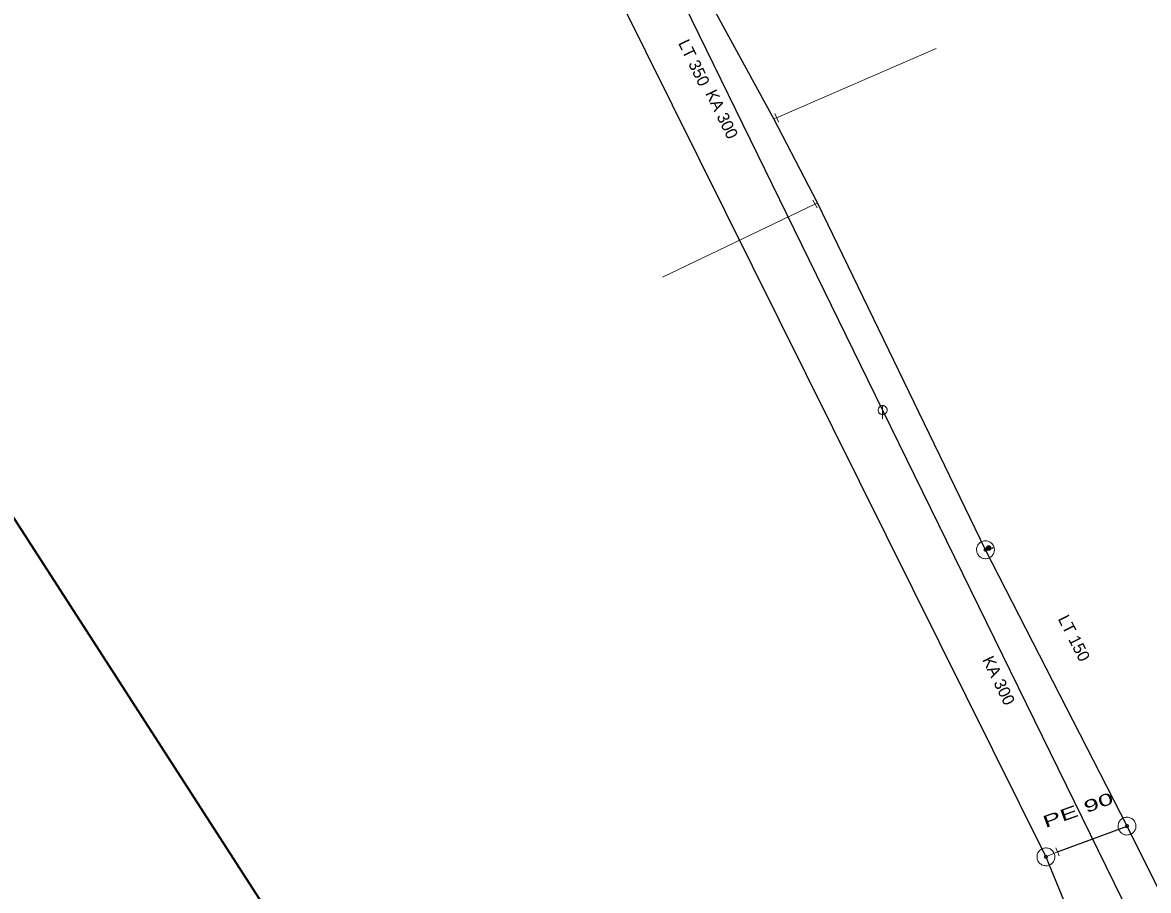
# Model space of a CAD drawing. Extents: x -687468 to -685917, y -974192 to -973456.
# Drawn here: x -686146.9 to -686083.7, y -973629.5 to -973580.8 of the extents above; entities that cross this region are included whole.
import ezdxf
from ezdxf.enums import TextEntityAlignment as Align

# ---------------------------------------------------------------- set-up
doc = ezdxf.new("R2010")
doc.units = 0
doc.header["$LTSCALE"] = 0.27
for name, color, linetype, lineweight in [('1', 7, 'Continuous', 13), ('13', 7, 'Continuous', 13), ('14', 7, 'Continuous', 25), ('17', 7, 'Continuous', 25), ('22', 7, 'Continuous', 13), ('34', 7, 'Continuous', 13), ('47', 7, 'Continuous', 13), ('9', 7, 'Continuous', 13)]:
    doc.layers.add(name, color=color, linetype=linetype, lineweight=lineweight)

msp = doc.modelspace()

# ---------------------------------------------------------------- linework, layer by layer
at = {"layer": '13'}
for p, q in [((-686104.569, -973586.101), (-686095.624, -973582.228)), ((-686102.416, -973590.949), (-686110.964, -973595.047))]:
    msp.add_line(p, q, dxfattribs=at)
at = {"layer": '14', "lineweight": 13}
for p, q in [((-686104.723, -973586.169), (-686104.569, -973586.101)), ((-686102.274, -973590.875), (-686102.416, -973590.949)), ((-686092.851, -973610.351), (-686092.667, -973610.253)), ((-686089.459, -973627.585), (-686088.809, -973627.309))]:
    msp.add_line(p, q, dxfattribs=at)
at = {"layer": '14'}
msp.add_line((-686098.62, -973602.51), (-686082.39, -973635.68), dxfattribs=at)
msp.add_lwpolyline([(-686121.14, -973557.36), (-686113.805, -973571.474), (-686113.469, -973572.12), (-686098.62, -973602.51)], dxfattribs=at)
at = {"layer": '17'}
for p, q in [((-686130.979, -973544.009), (-686089.459, -973627.585)), ((-686084.908, -973625.859), (-686092.851, -973610.351)), ((-686088.809, -973627.309), (-686084.908, -973625.859))]:
    msp.add_line(p, q, dxfattribs=at)
for points in [[(-686092.851, -973610.351), (-686102.274, -973590.875), (-686104.723, -973586.169), (-686124.519, -973549.959)], [(-686051.061, -973652.866), (-686059.705, -973650.715), (-686071.797, -973646.764), (-686075.022, -973645.71), (-686084.908, -973625.859)], [(-686089.459, -973627.585), (-686086.411, -973635.017), (-686086.079, -973650.552), (-686091.072, -973716.745), (-686088.221, -973728.447), (-686086.081, -973747.168), (-686087.506, -973758.201), (-686097.397, -973770.949)]]:
    msp.add_lwpolyline(points, dxfattribs=at)
at = {"layer": '17', "lineweight": 35}
msp.add_lwpolyline([(-686160.425, -973551.891), (-686169.469, -973574.282), (-686122.999, -973646.384), (-686098.932, -973712.353), (-686089.329, -973782.048), (-686297.791, -974027.806), (-686326.807, -974076.614), (-686379.703, -974100.561), (-686411.584, -974111.413)], dxfattribs=at)
at = {"layer": '22'}
msp.add_line((-686098.619, -973602.258), (-686098.62, -973603.002), dxfattribs=at)
msp.add_lwpolyline([(-686098.368, -973602.51), (-686098.369, -973602.484), (-686098.373, -973602.458), (-686098.379, -973602.432), (-686098.389, -973602.408), (-686098.401, -973602.384), (-686098.415, -973602.362), (-686098.432, -973602.341), (-686098.45, -973602.323), (-686098.471, -973602.306), (-686098.493, -973602.292), (-686098.517, -973602.28), (-686098.541, -973602.27), (-686098.567, -973602.264), (-686098.593, -973602.26), (-686098.619, -973602.258), (-686098.645, -973602.259), (-686098.671, -973602.263), (-686098.697, -973602.269), (-686098.722, -973602.279), (-686098.745, -973602.291), (-686098.767, -973602.305), (-686098.788, -973602.322), (-686098.806, -973602.34), (-686098.823, -973602.361), (-686098.837, -973602.383), (-686098.849, -973602.407), (-686098.859, -973602.431), (-686098.866, -973602.457), (-686098.87, -973602.483), (-686098.872, -973602.509), (-686098.871, -973602.535), (-686098.867, -973602.561), (-686098.86, -973602.587), (-686098.85, -973602.612), (-686098.838, -973602.635), (-686098.824, -973602.657), (-686098.807, -973602.678), (-686098.789, -973602.696), (-686098.768, -973602.713), (-686098.746, -973602.727), (-686098.723, -973602.739), (-686098.698, -973602.749), (-686098.672, -973602.756), (-686098.646, -973602.76), (-686098.62, -973602.762), (-686098.594, -973602.761), (-686098.568, -973602.757), (-686098.542, -973602.75), (-686098.518, -973602.74), (-686098.494, -973602.728), (-686098.472, -973602.714), (-686098.451, -973602.697), (-686098.433, -973602.679), (-686098.416, -973602.658), (-686098.402, -973602.636), (-686098.39, -973602.613), (-686098.38, -973602.588), (-686098.374, -973602.562), (-686098.37, -973602.536)], close=True, dxfattribs=at)
at = {"layer": '34'}
for p, q in [((-686104.468, -973586.327), (-686104.669, -973585.874)), ((-686102.53, -973590.729), (-686102.301, -973591.168)), ((-686088.706, -973627.534), (-686088.911, -973627.083))]:
    msp.add_line(p, q, dxfattribs=at)
at = {"layer": '47'}
for points in [[(-686093.078, -973609.905), (-686093.123, -973609.932), (-686093.166, -973609.963), (-686093.204, -973609.998), (-686093.24, -973610.036), (-686093.27, -973610.079), (-686093.296, -973610.125), (-686093.317, -973610.173), (-686093.333, -973610.222), (-686093.344, -973610.273), (-686093.35, -973610.325), (-686093.35, -973610.378), (-686093.343, -973610.43), (-686093.333, -973610.481), (-686093.317, -973610.531), (-686093.296, -973610.578), (-686093.269, -973610.623), (-686093.238, -973610.666), (-686093.203, -973610.705), (-686093.165, -973610.74), (-686093.122, -973610.77), (-686093.076, -973610.796), (-686093.028, -973610.818), (-686092.978, -973610.834), (-686092.928, -973610.845), (-686092.876, -973610.85), (-686092.823, -973610.85), (-686092.771, -973610.844), (-686092.72, -973610.833), (-686092.67, -973610.817), (-686092.623, -973610.796), (-686092.578, -973610.769), (-686092.535, -973610.738), (-686092.496, -973610.704), (-686092.461, -973610.665), (-686092.431, -973610.622), (-686092.404, -973610.577), (-686092.383, -973610.529), (-686092.367, -973610.479), (-686092.356, -973610.428), (-686092.351, -973610.376), (-686092.351, -973610.323), (-686092.356, -973610.271), (-686092.368, -973610.22), (-686092.384, -973610.17), (-686092.405, -973610.123), (-686092.432, -973610.078), (-686092.463, -973610.035), (-686092.497, -973609.996), (-686092.536, -973609.961), (-686092.579, -973609.931), (-686092.624, -973609.904), (-686092.672, -973609.884), (-686092.721, -973609.868), (-686092.773, -973609.857), (-686092.825, -973609.851), (-686092.878, -973609.851), (-686092.929, -973609.857), (-686092.981, -973609.868), (-686093.031, -973609.884)], [(-686092.888, -973610.278), (-686092.896, -973610.282), (-686092.902, -973610.287), (-686092.908, -973610.292), (-686092.914, -973610.299), (-686092.919, -973610.306), (-686092.923, -973610.314), (-686092.927, -973610.321), (-686092.93, -973610.329), (-686092.931, -973610.338), (-686092.932, -973610.346), (-686092.932, -973610.355), (-686092.931, -973610.364), (-686092.929, -973610.372), (-686092.928, -973610.38), (-686092.923, -973610.388), (-686092.919, -973610.396), (-686092.914, -973610.402), (-686092.909, -973610.408), (-686092.902, -973610.414), (-686092.895, -973610.419), (-686092.887, -973610.423), (-686092.88, -973610.427), (-686092.872, -973610.43), (-686092.863, -973610.432), (-686092.855, -973610.432), (-686092.846, -973610.432), (-686092.837, -973610.431), (-686092.829, -973610.429), (-686092.821, -973610.428), (-686092.813, -973610.423), (-686092.805, -973610.419), (-686092.799, -973610.414), (-686092.793, -973610.409), (-686092.787, -973610.402), (-686092.782, -973610.395), (-686092.777, -973610.388), (-686092.774, -973610.38), (-686092.771, -973610.372), (-686092.769, -973610.363), (-686092.769, -973610.355), (-686092.769, -973610.346), (-686092.77, -973610.337), (-686092.772, -973610.329), (-686092.773, -973610.321), (-686092.778, -973610.313), (-686092.782, -973610.305), (-686092.787, -973610.299), (-686092.792, -973610.293), (-686092.799, -973610.287), (-686092.806, -973610.282), (-686092.813, -973610.277), (-686092.821, -973610.274), (-686092.829, -973610.271), (-686092.838, -973610.27), (-686092.846, -973610.269), (-686092.855, -973610.269), (-686092.864, -973610.27), (-686092.872, -973610.272), (-686092.88, -973610.273)], [(-686084.668, -973626.297), (-686084.624, -973626.27), (-686084.582, -973626.238), (-686084.545, -973626.202), (-686084.51, -973626.162), (-686084.481, -973626.119), (-686084.456, -973626.072), (-686084.437, -973626.024), (-686084.422, -973625.974), (-686084.412, -973625.923), (-686084.408, -973625.87), (-686084.409, -973625.818), (-686084.417, -973625.766), (-686084.428, -973625.715), (-686084.446, -973625.666), (-686084.469, -973625.619), (-686084.496, -973625.575), (-686084.528, -973625.533), (-686084.565, -973625.495), (-686084.604, -973625.461), (-686084.647, -973625.432), (-686084.694, -973625.407), (-686084.742, -973625.387), (-686084.793, -973625.372), (-686084.844, -973625.362), (-686084.896, -973625.359), (-686084.948, -973625.36), (-686085, -973625.367), (-686085.051, -973625.379), (-686085.1, -973625.397), (-686085.147, -973625.42), (-686085.191, -973625.447), (-686085.233, -973625.479), (-686085.272, -973625.515), (-686085.305, -973625.555), (-686085.334, -973625.598), (-686085.36, -973625.644), (-686085.38, -973625.693), (-686085.395, -973625.743), (-686085.404, -973625.795), (-686085.407, -973625.847), (-686085.406, -973625.899), (-686085.4, -973625.951), (-686085.387, -973626.002), (-686085.369, -973626.051), (-686085.346, -973626.098), (-686085.319, -973626.142), (-686085.287, -973626.184), (-686085.251, -973626.222), (-686085.211, -973626.256), (-686085.168, -973626.285), (-686085.122, -973626.311), (-686085.074, -973626.33), (-686085.024, -973626.345), (-686084.972, -973626.354), (-686084.919, -973626.358), (-686084.867, -973626.357), (-686084.816, -973626.35), (-686084.764, -973626.338), (-686084.715, -973626.32)], [(-686084.868, -973625.93), (-686084.86, -973625.926), (-686084.854, -973625.921), (-686084.848, -973625.915), (-686084.843, -973625.909), (-686084.837, -973625.901), (-686084.834, -973625.893), (-686084.83, -973625.886), (-686084.828, -973625.878), (-686084.827, -973625.869), (-686084.826, -973625.86), (-686084.826, -973625.852), (-686084.827, -973625.843), (-686084.829, -973625.835), (-686084.831, -973625.827), (-686084.836, -973625.819), (-686084.84, -973625.811), (-686084.845, -973625.805), (-686084.851, -973625.799), (-686084.857, -973625.794), (-686084.865, -973625.788), (-686084.873, -973625.785), (-686084.88, -973625.781), (-686084.888, -973625.779), (-686084.897, -973625.777), (-686084.906, -973625.777), (-686084.914, -973625.777), (-686084.923, -973625.778), (-686084.931, -973625.78), (-686084.939, -973625.782), (-686084.947, -973625.787), (-686084.955, -973625.791), (-686084.961, -973625.796), (-686084.967, -973625.802), (-686084.972, -973625.808), (-686084.978, -973625.816), (-686084.982, -973625.823), (-686084.985, -973625.831), (-686084.987, -973625.839), (-686084.989, -973625.848), (-686084.989, -973625.857), (-686084.989, -973625.865), (-686084.988, -973625.874), (-686084.986, -973625.882), (-686084.984, -973625.89), (-686084.979, -973625.898), (-686084.975, -973625.906), (-686084.97, -973625.912), (-686084.964, -973625.918), (-686084.958, -973625.923), (-686084.95, -973625.929), (-686084.943, -973625.933), (-686084.935, -973625.936), (-686084.927, -973625.938), (-686084.918, -973625.939), (-686084.909, -973625.94), (-686084.901, -973625.94), (-686084.892, -973625.939), (-686084.884, -973625.937), (-686084.876, -973625.935)], [(-686089.234, -973628.031), (-686089.189, -973628.005), (-686089.146, -973627.975), (-686089.108, -973627.94), (-686089.072, -973627.902), (-686089.041, -973627.859), (-686089.015, -973627.814), (-686088.994, -973627.766), (-686088.977, -973627.717), (-686088.966, -973627.666), (-686088.959, -973627.614), (-686088.959, -973627.561), (-686088.965, -973627.509), (-686088.975, -973627.458), (-686088.991, -973627.408), (-686089.012, -973627.36), (-686089.038, -973627.315), (-686089.068, -973627.272), (-686089.103, -973627.233), (-686089.141, -973627.198), (-686089.184, -973627.167), (-686089.229, -973627.141), (-686089.277, -973627.119), (-686089.327, -973627.102), (-686089.377, -973627.091), (-686089.429, -973627.085), (-686089.482, -973627.085), (-686089.534, -973627.09), (-686089.585, -973627.101), (-686089.635, -973627.117), (-686089.683, -973627.138), (-686089.728, -973627.164), (-686089.771, -973627.194), (-686089.81, -973627.228), (-686089.845, -973627.267), (-686089.876, -973627.31), (-686089.903, -973627.354), (-686089.925, -973627.402), (-686089.941, -973627.452), (-686089.952, -973627.503), (-686089.958, -973627.555), (-686089.958, -973627.608), (-686089.953, -973627.659), (-686089.942, -973627.711), (-686089.926, -973627.761), (-686089.905, -973627.809), (-686089.879, -973627.854), (-686089.849, -973627.897), (-686089.815, -973627.936), (-686089.776, -973627.971), (-686089.733, -973628.002), (-686089.689, -973628.029), (-686089.641, -973628.05), (-686089.592, -973628.066), (-686089.54, -973628.077), (-686089.488, -973628.084), (-686089.435, -973628.084), (-686089.384, -973628.079), (-686089.332, -973628.068), (-686089.282, -973628.052)], [(-686089.422, -973627.658), (-686089.414, -973627.654), (-686089.407, -973627.648), (-686089.401, -973627.643), (-686089.395, -973627.637), (-686089.39, -973627.63), (-686089.386, -973627.622), (-686089.382, -973627.614), (-686089.379, -973627.606), (-686089.378, -973627.598), (-686089.377, -973627.589), (-686089.377, -973627.58), (-686089.378, -973627.572), (-686089.379, -973627.564), (-686089.381, -973627.556), (-686089.385, -973627.548), (-686089.389, -973627.54), (-686089.395, -973627.533), (-686089.4, -973627.527), (-686089.406, -973627.521), (-686089.413, -973627.516), (-686089.421, -973627.512), (-686089.429, -973627.508), (-686089.437, -973627.505), (-686089.446, -973627.503), (-686089.454, -973627.503), (-686089.463, -973627.503), (-686089.471, -973627.504), (-686089.479, -973627.505), (-686089.487, -973627.507), (-686089.495, -973627.511), (-686089.503, -973627.515), (-686089.51, -973627.521), (-686089.516, -973627.526), (-686089.522, -973627.532), (-686089.527, -973627.539), (-686089.531, -973627.546), (-686089.535, -973627.555), (-686089.538, -973627.563), (-686089.54, -973627.572), (-686089.54, -973627.58), (-686089.54, -973627.589), (-686089.539, -973627.597), (-686089.538, -973627.605), (-686089.536, -973627.613), (-686089.532, -973627.621), (-686089.528, -973627.629), (-686089.522, -973627.636), (-686089.517, -973627.642), (-686089.511, -973627.648), (-686089.504, -973627.653), (-686089.497, -973627.657), (-686089.488, -973627.661), (-686089.48, -973627.664), (-686089.472, -973627.665), (-686089.463, -973627.666), (-686089.454, -973627.666), (-686089.446, -973627.665), (-686089.438, -973627.664), (-686089.43, -973627.662)]]:
    msp.add_lwpolyline(points, close=True, dxfattribs=at)
at = {"layer": '9'}
msp.add_line((-686092.541, -973610.253), (-686092.415, -973610.253), dxfattribs=at)
for points in [[(-686092.667, -973610.379), (-686092.654, -973610.378), (-686092.641, -973610.376), (-686092.628, -973610.373), (-686092.616, -973610.368), (-686092.604, -973610.362), (-686092.593, -973610.355), (-686092.583, -973610.347), (-686092.573, -973610.337), (-686092.565, -973610.327), (-686092.558, -973610.316), (-686092.552, -973610.304), (-686092.547, -973610.292), (-686092.544, -973610.279), (-686092.542, -973610.266), (-686092.541, -973610.253), (-686092.541, -973610.24), (-686092.543, -973610.227), (-686092.546, -973610.214), (-686092.551, -973610.202), (-686092.557, -973610.19), (-686092.564, -973610.179), (-686092.572, -973610.169), (-686092.582, -973610.159), (-686092.592, -973610.151), (-686092.603, -973610.144), (-686092.615, -973610.138), (-686092.627, -973610.133), (-686092.64, -973610.13), (-686092.653, -973610.128), (-686092.666, -973610.127), (-686092.679, -973610.127), (-686092.692, -973610.129), (-686092.705, -973610.132), (-686092.717, -973610.137), (-686092.729, -973610.143), (-686092.74, -973610.15), (-686092.75, -973610.158), (-686092.76, -973610.168), (-686092.768, -973610.178), (-686092.775, -973610.189), (-686092.781, -973610.201), (-686092.786, -973610.213), (-686092.789, -973610.226), (-686092.791, -973610.239), (-686092.793, -973610.252), (-686092.792, -973610.265), (-686092.79, -973610.278), (-686092.787, -973610.291), (-686092.782, -973610.303), (-686092.776, -973610.315), (-686092.769, -973610.326), (-686092.761, -973610.336), (-686092.751, -973610.346), (-686092.741, -973610.354), (-686092.73, -973610.361), (-686092.718, -973610.367), (-686092.706, -973610.372), (-686092.693, -973610.375), (-686092.68, -973610.377)], [(-686092.667, -973610.359), (-686092.656, -973610.359), (-686092.645, -973610.357), (-686092.634, -973610.354), (-686092.624, -973610.35), (-686092.614, -973610.345), (-686092.605, -973610.339), (-686092.596, -973610.332), (-686092.588, -973610.324), (-686092.581, -973610.315), (-686092.575, -973610.306), (-686092.57, -973610.296), (-686092.566, -973610.286), (-686092.563, -973610.275), (-686092.561, -973610.264), (-686092.561, -973610.253), (-686092.56, -973610.242), (-686092.562, -973610.231), (-686092.565, -973610.22), (-686092.569, -973610.21), (-686092.574, -973610.2), (-686092.58, -973610.191), (-686092.587, -973610.182), (-686092.595, -973610.174), (-686092.604, -973610.167), (-686092.613, -973610.161), (-686092.623, -973610.156), (-686092.633, -973610.152), (-686092.644, -973610.149), (-686092.655, -973610.147), (-686092.666, -973610.147), (-686092.677, -973610.146), (-686092.688, -973610.148), (-686092.699, -973610.151), (-686092.709, -973610.155), (-686092.719, -973610.16), (-686092.728, -973610.166), (-686092.737, -973610.173), (-686092.745, -973610.181), (-686092.752, -973610.19), (-686092.758, -973610.199), (-686092.763, -973610.209), (-686092.767, -973610.219), (-686092.77, -973610.23), (-686092.772, -973610.241), (-686092.773, -973610.252), (-686092.773, -973610.263), (-686092.771, -973610.274), (-686092.768, -973610.285), (-686092.764, -973610.295), (-686092.759, -973610.305), (-686092.753, -973610.314), (-686092.746, -973610.323), (-686092.738, -973610.331), (-686092.729, -973610.338), (-686092.72, -973610.344), (-686092.71, -973610.349), (-686092.7, -973610.353), (-686092.689, -973610.356), (-686092.678, -973610.358)], [(-686092.667, -973610.34), (-686092.658, -973610.339), (-686092.649, -973610.338), (-686092.64, -973610.335), (-686092.632, -973610.332), (-686092.624, -973610.328), (-686092.616, -973610.323), (-686092.609, -973610.317), (-686092.603, -973610.311), (-686092.597, -973610.304), (-686092.592, -973610.296), (-686092.588, -973610.288), (-686092.585, -973610.28), (-686092.582, -973610.271), (-686092.581, -973610.262), (-686092.58, -973610.253), (-686092.58, -973610.244), (-686092.581, -973610.235), (-686092.584, -973610.226), (-686092.587, -973610.218), (-686092.591, -973610.21), (-686092.596, -973610.202), (-686092.602, -973610.195), (-686092.608, -973610.189), (-686092.615, -973610.183), (-686092.623, -973610.178), (-686092.631, -973610.174), (-686092.639, -973610.171), (-686092.648, -973610.168), (-686092.657, -973610.167), (-686092.666, -973610.166), (-686092.675, -973610.166), (-686092.684, -973610.167), (-686092.693, -973610.17), (-686092.701, -973610.173), (-686092.709, -973610.177), (-686092.717, -973610.182), (-686092.724, -973610.188), (-686092.73, -973610.194), (-686092.736, -973610.201), (-686092.741, -973610.209), (-686092.745, -973610.217), (-686092.748, -973610.225), (-686092.751, -973610.234), (-686092.752, -973610.243), (-686092.754, -973610.252), (-686092.753, -973610.261), (-686092.752, -973610.27), (-686092.749, -973610.279), (-686092.746, -973610.287), (-686092.742, -973610.295), (-686092.737, -973610.303), (-686092.731, -973610.31), (-686092.725, -973610.316), (-686092.718, -973610.322), (-686092.71, -973610.327), (-686092.702, -973610.331), (-686092.694, -973610.334), (-686092.685, -973610.337), (-686092.676, -973610.338)], [(-686092.667, -973610.32), (-686092.66, -973610.32), (-686092.653, -973610.318), (-686092.646, -973610.317), (-686092.64, -973610.314), (-686092.634, -973610.311), (-686092.628, -973610.307), (-686092.622, -973610.303), (-686092.617, -973610.298), (-686092.613, -973610.292), (-686092.609, -973610.286), (-686092.606, -973610.28), (-686092.603, -973610.274), (-686092.602, -973610.267), (-686092.6, -973610.26), (-686092.6, -973610.253), (-686092.599, -973610.246), (-686092.601, -973610.239), (-686092.602, -973610.232), (-686092.605, -973610.226), (-686092.608, -973610.219), (-686092.612, -973610.214), (-686092.616, -973610.208), (-686092.621, -973610.203), (-686092.627, -973610.199), (-686092.633, -973610.195), (-686092.639, -973610.192), (-686092.645, -973610.189), (-686092.652, -973610.187), (-686092.659, -973610.186), (-686092.666, -973610.186), (-686092.673, -973610.185), (-686092.68, -973610.186), (-686092.687, -973610.188), (-686092.693, -973610.191), (-686092.7, -973610.194), (-686092.705, -973610.198), (-686092.711, -973610.202), (-686092.716, -973610.207), (-686092.72, -973610.213), (-686092.724, -973610.218), (-686092.727, -973610.225), (-686092.73, -973610.231), (-686092.732, -973610.238), (-686092.733, -973610.245), (-686092.734, -973610.252), (-686092.734, -973610.259), (-686092.733, -973610.266), (-686092.731, -973610.273), (-686092.728, -973610.279), (-686092.725, -973610.285), (-686092.721, -973610.291), (-686092.717, -973610.297), (-686092.712, -973610.302), (-686092.706, -973610.306), (-686092.701, -973610.31), (-686092.694, -973610.313), (-686092.688, -973610.316), (-686092.681, -973610.317), (-686092.674, -973610.319)], [(-686092.667, -973610.3), (-686092.662, -973610.3), (-686092.657, -973610.299), (-686092.652, -973610.298), (-686092.648, -973610.296), (-686092.643, -973610.294), (-686092.639, -973610.291), (-686092.636, -973610.288), (-686092.632, -973610.284), (-686092.629, -973610.281), (-686092.626, -973610.277), (-686092.624, -973610.272), (-686092.622, -973610.268), (-686092.621, -973610.263), (-686092.62, -973610.258), (-686092.62, -973610.253), (-686092.619, -973610.248), (-686092.62, -973610.243), (-686092.621, -973610.238), (-686092.623, -973610.234), (-686092.625, -973610.229), (-686092.628, -973610.225), (-686092.631, -973610.221), (-686092.635, -973610.218), (-686092.638, -973610.215), (-686092.642, -973610.212), (-686092.647, -973610.21), (-686092.651, -973610.208), (-686092.656, -973610.207), (-686092.661, -973610.206), (-686092.666, -973610.206), (-686092.671, -973610.205), (-686092.676, -973610.206), (-686092.681, -973610.207), (-686092.685, -973610.209), (-686092.69, -973610.211), (-686092.694, -973610.214), (-686092.698, -973610.217), (-686092.701, -973610.22), (-686092.704, -973610.224), (-686092.707, -973610.228), (-686092.709, -973610.233), (-686092.711, -973610.237), (-686092.712, -973610.242), (-686092.713, -973610.247), (-686092.714, -973610.252), (-686092.714, -973610.257), (-686092.713, -973610.262), (-686092.712, -973610.267), (-686092.71, -973610.271), (-686092.708, -973610.276), (-686092.705, -973610.28), (-686092.702, -973610.283), (-686092.699, -973610.287), (-686092.695, -973610.29), (-686092.691, -973610.293), (-686092.686, -973610.295), (-686092.682, -973610.297), (-686092.677, -973610.298), (-686092.672, -973610.299)], [(-686092.667, -973610.28), (-686092.664, -973610.28), (-686092.661, -973610.28), (-686092.659, -973610.279), (-686092.656, -973610.278), (-686092.653, -973610.277), (-686092.651, -973610.275), (-686092.649, -973610.273), (-686092.647, -973610.271), (-686092.645, -973610.269), (-686092.643, -973610.267), (-686092.642, -973610.264), (-686092.641, -973610.261), (-686092.64, -973610.259), (-686092.64, -973610.256), (-686092.64, -973610.253), (-686092.639, -973610.25), (-686092.639, -973610.247), (-686092.64, -973610.244), (-686092.641, -973610.242), (-686092.642, -973610.239), (-686092.644, -973610.237), (-686092.646, -973610.234), (-686092.648, -973610.232), (-686092.65, -973610.231), (-686092.652, -973610.229), (-686092.655, -973610.228), (-686092.658, -973610.227), (-686092.66, -973610.226), (-686092.663, -973610.226), (-686092.666, -973610.225), (-686092.669, -973610.225), (-686092.672, -973610.225), (-686092.675, -973610.226), (-686092.677, -973610.227), (-686092.68, -973610.228), (-686092.682, -973610.23), (-686092.685, -973610.231), (-686092.687, -973610.233), (-686092.688, -973610.236), (-686092.69, -973610.238), (-686092.691, -973610.241), (-686092.692, -973610.243), (-686092.693, -973610.246), (-686092.693, -973610.249), (-686092.695, -973610.252), (-686092.694, -973610.255), (-686092.694, -973610.258), (-686092.693, -973610.26), (-686092.692, -973610.263), (-686092.691, -973610.266), (-686092.689, -973610.268), (-686092.688, -973610.27), (-686092.686, -973610.272), (-686092.683, -973610.274), (-686092.681, -973610.276), (-686092.678, -973610.277), (-686092.676, -973610.278), (-686092.673, -973610.279), (-686092.67, -973610.279)], [(-686092.667, -973610.261), (-686092.666, -973610.261), (-686092.665, -973610.261), (-686092.665, -973610.26), (-686092.664, -973610.26), (-686092.663, -973610.26), (-686092.662, -973610.259), (-686092.662, -973610.259), (-686092.661, -973610.258), (-686092.661, -973610.258), (-686092.66, -973610.257), (-686092.66, -973610.256), (-686092.66, -973610.255), (-686092.659, -973610.255), (-686092.659, -973610.254), (-686092.659, -973610.253), (-686092.659, -973610.252), (-686092.659, -973610.251), (-686092.659, -973610.251), (-686092.659, -973610.25), (-686092.659, -973610.249), (-686092.66, -973610.248), (-686092.66, -973610.248), (-686092.661, -973610.247), (-686092.661, -973610.247), (-686092.662, -973610.246), (-686092.663, -973610.246), (-686092.664, -973610.245), (-686092.664, -973610.245), (-686092.665, -973610.245), (-686092.666, -973610.245), (-686092.667, -973610.245), (-686092.668, -973610.245), (-686092.668, -973610.245), (-686092.669, -973610.245), (-686092.67, -973610.245), (-686092.671, -973610.246), (-686092.671, -973610.246), (-686092.672, -973610.247), (-686092.672, -973610.247), (-686092.673, -973610.248), (-686092.673, -973610.249), (-686092.674, -973610.25), (-686092.674, -973610.25), (-686092.674, -973610.251), (-686092.675, -973610.252), (-686092.675, -973610.253), (-686092.675, -973610.254), (-686092.675, -973610.254), (-686092.674, -973610.255), (-686092.674, -973610.256), (-686092.673, -973610.257), (-686092.673, -973610.257), (-686092.672, -973610.258), (-686092.672, -973610.258), (-686092.671, -973610.259), (-686092.67, -973610.259), (-686092.669, -973610.259), (-686092.669, -973610.261), (-686092.668, -973610.261)]]:
    msp.add_lwpolyline(points, close=True, dxfattribs=at)
msp.add_lwpolyline([(-686092.449, -973610.222), (-686092.415, -973610.253), (-686092.45, -973610.284)], dxfattribs=at)

# ---------------------------------------------------------------- texts
at = {"layer": '1'}
for s, rotation, p in [('LT 350', 296, (-686109.498, -973583.162)), ('KA 300', 296, (-686107.94, -973586.052)), ('LT 150', 297, (-686088.175, -973615.459)), ('KA 300', 296, (-686092.402, -973617.833))]:
    msp.add_text(s, height=0.6667, rotation=rotation, dxfattribs=at).set_placement(p, align=Align.CENTER)
at = {"layer": '1', "width": 1.7}
msp.add_text('PE 90 ', height=0.6667, rotation=20, dxfattribs=at).set_placement((-686087.346, -973625.192), align=Align.CENTER)

doc.saveas('drawing.dxf')
